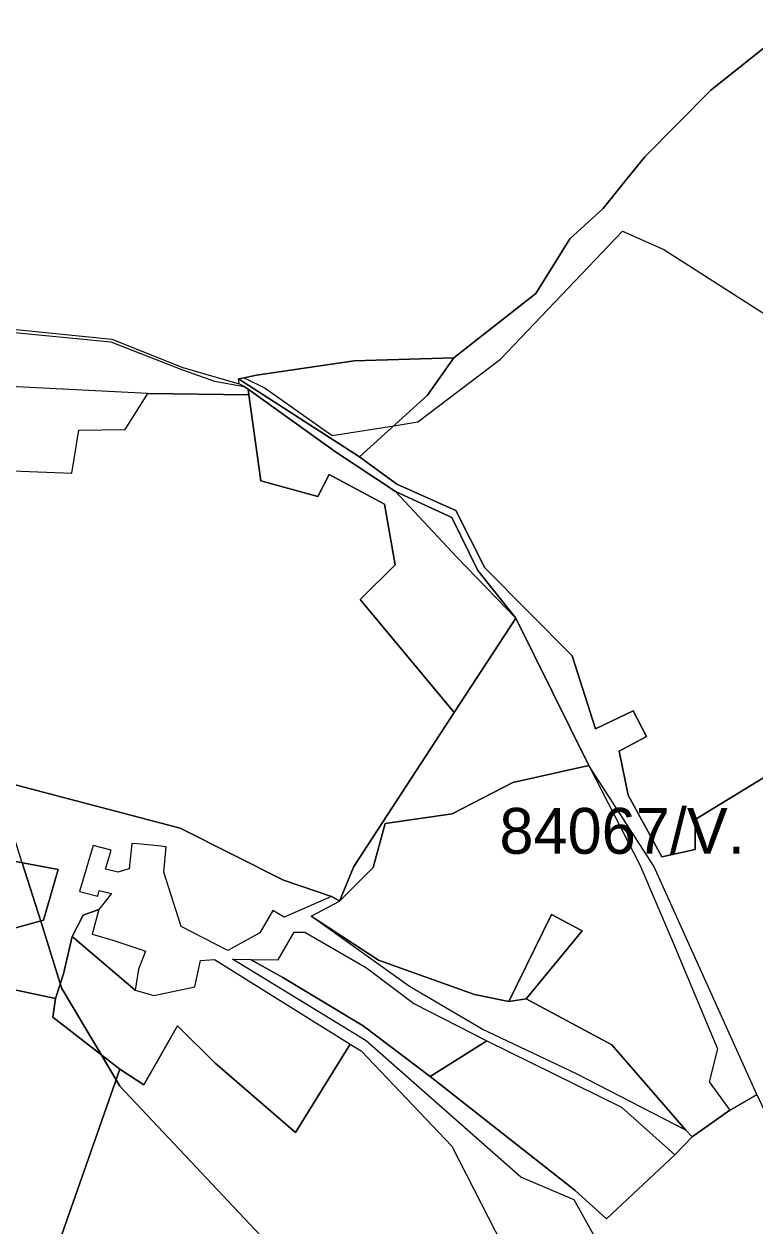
# Model space of a CAD drawing. Extents: x -477304 to -465429, y -1159113 to -1149210.
# Drawn here: x -476359.9 to -476120.7, y -1150940.8 to -1150547.2 of the extents above; entities that cross this region are included whole.
import ezdxf

# ---------------------------------------------------------------- set-up
doc = ezdxf.new("R2010")
doc.units = 0
for name, color, linetype in [('BPEJ_s', 7, 'Continuous'), ('PUPFL_s', 7, 'Continuous'), ('trav_porost_s', 7, 'Continuous')]:
    doc.layers.add(name, color=color, linetype=linetype)

msp = doc.modelspace()

# ---------------------------------------------------------------- linework, layer by layer
at = {"layer": 'BPEJ_s'}
for points in [[(-476107.95, -1150547.2), (-476135.12, -1150568.82), (-476156.76, -1150590.66), (-476163.4, -1150598.92), (-476170.36, -1150607.63), (-476181.22, -1150617.52), (-476192.35, -1150635.43), (-476210.07, -1150649.35), (-476219.17, -1150656.5), (-476251.83, -1150657.52), (-476283.76, -1150662.23), (-476285.3, -1150662.53), (-476287.79, -1150663.02), (-476289.73, -1150663.4), (-476287.82, -1150663.03), (-476287.57, -1150663.16), (-476281, -1150666.5), (-476259, -1150682), (-476238.87, -1150678.77), (-476231, -1150677.5), (-476204, -1150657), (-476164, -1150615), (-476150.5, -1150621), (-476107.5, -1150648.5)], [(-476373.37, -1150646.18), (-476331.18, -1150650.38), (-476307.91, -1150659.69), (-476289.46, -1150665.08), (-476289.73, -1150663.4), (-476287.82, -1150663.03), (-476287.57, -1150663.16), (-476281, -1150666.5), (-476259, -1150682), (-476238.87, -1150678.77), (-476231, -1150677.5), (-476204, -1150657), (-476164, -1150615), (-476150.5, -1150621), (-476107.5, -1150648.5)], [(-476261.1, -1150966.61), (-476328.5, -1150895), (-476329.74, -1150892.92), (-476334.63, -1150884.68), (-476347.5, -1150863), (-476348.01, -1150861.37), (-476354.43, -1150840.98), (-476360.45, -1150821.88), (-476364.5, -1150809), (-476371.2, -1150793.93), (-476374.5, -1150786.5), (-476395, -1150762)], [(-476360.45, -1150821.88), (-476354.43, -1150840.98), (-476348.01, -1150861.37), (-476347.5, -1150863), (-476334.63, -1150884.68), (-476329.74, -1150892.92), (-476328.5, -1150895), (-476261.1, -1150966.61)]]:
    msp.add_lwpolyline(points, dxfattribs=at)
at = {"layer": 'PUPFL_s'}
for points in [[(-476109.7, -1150789.06), (-476140.24, -1150807.74), (-476140.24, -1150817.52), (-476151.2, -1150819.98), (-476162.13, -1150799.7), (-476165.16, -1150785.3), (-476156.19, -1150780.52), (-476160.57, -1150772.14), (-476172.83, -1150777.96), (-476180.54, -1150754.15), (-476209.12, -1150725.33), (-476218.52, -1150706.51), (-476237.9, -1150697.94), (-476250.15, -1150688.99), (-476227.84, -1150668.76), (-476219.17, -1150656.5), (-476210.07, -1150649.35), (-476192.35, -1150635.43), (-476181.22, -1150617.52), (-476170.36, -1150607.63), (-476163.4, -1150598.92), (-476156.76, -1150590.66), (-476135.12, -1150568.82), (-476107.95, -1150547.2)], [(-476120.01, -1150897.77), (-476122.03, -1150893.44), (-476153.81, -1150822.97), (-476175.03, -1150790), (-476198.9, -1150741.72), (-476211.35, -1150726.19), (-476219.89, -1150708.83), (-476238.35, -1150700.34), (-476257.91, -1150687.26), (-476286.58, -1150666.82), (-476287.88, -1150665.9), (-476289.46, -1150665.08), (-476289.73, -1150663.4), (-476250.15, -1150688.99), (-476237.9, -1150697.94), (-476218.52, -1150706.51), (-476209.12, -1150725.33), (-476180.54, -1150754.15), (-476172.83, -1150777.96), (-476160.57, -1150772.14), (-476156.19, -1150780.52), (-476165.16, -1150785.3), (-476162.13, -1150799.7), (-476151.2, -1150819.98), (-476140.24, -1150817.52), (-476140.24, -1150807.74), (-476109.7, -1150789.06)]]:
    msp.add_lwpolyline(points, dxfattribs=at)
for points in [[(-476283.76, -1150662.23), (-476251.83, -1150657.52), (-476219.17, -1150656.5), (-476227.84, -1150668.76), (-476250.15, -1150688.99), (-476289.73, -1150663.4), (-476287.79, -1150663.02), (-476285.3, -1150662.53)], [(-476238.35, -1150700.34), (-476218.34, -1150721.71), (-476198.9, -1150741.72), (-476219.12, -1150772.7), (-476249.87, -1150735.64), (-476238.44, -1150724.3), (-476241.86, -1150704.39), (-476259.97, -1150694.68), (-476263.72, -1150701.89), (-476282.43, -1150696.77), (-476286.32, -1150668.68), (-476286.58, -1150666.82), (-476257.91, -1150687.26)], [(-476218.34, -1150721.71), (-476238.35, -1150700.34), (-476219.89, -1150708.83), (-476211.35, -1150726.19), (-476198.9, -1150741.72)], [(-476199.86, -1150795.58), (-476219.76, -1150805.85), (-476241.71, -1150809.04), (-476245.66, -1150823.44), (-476256.62, -1150834.5), (-476251.98, -1150823.07), (-476219.12, -1150772.7), (-476198.9, -1150741.72), (-476175.03, -1150790)]]:
    msp.add_lwpolyline(points, close=True, dxfattribs=at)
at = {"layer": 'trav_porost_s'}
for points in [[(-476378.07, -1150646.84), (-476365.14, -1150647.97), (-476331.49, -1150651.25), (-476308.07, -1150660.46), (-476297.58, -1150664.15), (-476287.88, -1150665.9), (-476286.58, -1150666.82), (-476286.32, -1150668.68), (-476319.32, -1150668.25), (-476368.8, -1150665.69), (-476386.61, -1150667.75), (-476421.17, -1150662.33), (-476465.43, -1150647.97), (-476496.07, -1150646.31), (-476490.9, -1150642.48), (-476468.87, -1150629.42), (-476490.17, -1150603.42), (-476500.39, -1150593.29), (-476489.18, -1150602.81), (-476474.07, -1150615.61), (-476468.67, -1150621.23), (-476445.25, -1150633.29), (-476428.52, -1150639.56), (-476412.6, -1150645.75)], [(-476219.76, -1150805.85), (-476199.86, -1150795.58), (-476175.03, -1150790), (-476158.38, -1150822.59), (-476147.46, -1150848.09), (-476132.96, -1150882.78), (-476135.65, -1150893.65), (-476128.94, -1150902.85), (-476141.2, -1150911.63), (-476143.34, -1150909.48), (-476167.49, -1150881.47), (-476195.53, -1150866.49), (-476177.27, -1150844.2), (-476187.22, -1150838.84), (-476201.26, -1150867.36), (-476212.41, -1150865.01), (-476243.93, -1150853.79), (-476265.87, -1150839.38), (-476256.62, -1150834.5), (-476245.66, -1150823.44), (-476241.71, -1150809.04)], [(-476353.49, -1150840.72), (-476366.17, -1150844.19), (-476362.73, -1150826.42), (-476381.3, -1150823.35), (-476380.67, -1150818.04), (-476348.74, -1150824.1)], [(-476322.42, -1150856.72), (-476323.55, -1150863.55), (-476344.14, -1150846.01), (-476340.54, -1150839.05), (-476335.4, -1150837.19), (-476337.61, -1150845.31), (-476330.78, -1150847.27), (-476321.94, -1150850.13), (-476320.08, -1150850.87)], [(-476233.78, -1150862.37), (-476265.87, -1150839.38), (-476243.93, -1150853.79), (-476212.41, -1150865.01), (-476201.26, -1150867.36), (-476195.53, -1150866.49), (-476167.49, -1150881.47), (-476143.34, -1150909.48), (-476179.11, -1150890.99), (-476210, -1150876.37)], [(-476201.26, -1150867.36), (-476187.22, -1150838.84), (-476177.27, -1150844.2), (-476195.53, -1150866.49)], [(-476349.63, -1150866.32), (-476347.01, -1150858.29), (-476344.14, -1150846.01), (-476323.55, -1150863.55), (-476317.43, -1150865.35), (-476304.02, -1150862.54), (-476302.1, -1150853.85), (-476297.58, -1150853.59), (-476253.14, -1150881.28), (-476271, -1150910.18), (-476297.42, -1150887.37), (-476309.67, -1150875.31), (-476320.67, -1150894.56), (-476328.51, -1150889.43), (-476350.43, -1150872.41)], [(-476247.78, -1150856.3), (-476232.27, -1150867.96), (-476208.42, -1150880.16), (-476226.98, -1150891.89), (-476248.92, -1150875.23), (-476275.15, -1150859.5), (-476285.76, -1150853.51), (-476276.66, -1150853.63), (-476271.43, -1150844.64), (-476268, -1150844.58)], [(-476291.66, -1150853.44), (-476285.76, -1150853.51), (-476275.15, -1150859.5), (-476248.92, -1150875.23), (-476226.98, -1150891.89), (-476179.52, -1150929.19), (-476169.27, -1150938.5), (-476146.89, -1150917.53), (-476141.2, -1150911.63), (-476128.94, -1150902.85), (-476120.01, -1150897.77), (-476105.17, -1150929.65), (-476058.51, -1150979.19), (-476050.49, -1150992.18), (-476075.81, -1150994.87), (-476131.48, -1150994.9), (-476151.58, -1150982.94), (-476179.85, -1150932.3), (-476197.3, -1150924.8), (-476247.95, -1150880.21)], [(-476371.22, -1150958.62), (-476371.72, -1150951.61), (-476371.19, -1150945.92), (-476384.56, -1150909.96), (-476384.75, -1150879.91), (-476385.1, -1150858.82), (-476349.63, -1150866.32), (-476350.43, -1150872.41), (-476328.51, -1150889.43), (-476357.03, -1150970.64)], [(-476226.98, -1150891.89), (-476208.42, -1150880.16), (-476164.31, -1150901.91), (-476146.89, -1150917.53), (-476169.27, -1150938.5), (-476179.52, -1150929.19)]]:
    msp.add_lwpolyline(points, close=True, dxfattribs=at)
for points in [[(-476380.43, -1150692.92), (-476344.28, -1150694.31), (-476341.95, -1150680.22), (-476326.8, -1150680.02), (-476319.32, -1150668.25), (-476286.32, -1150668.68), (-476282.43, -1150696.77), (-476263.72, -1150701.89), (-476259.97, -1150694.68), (-476241.86, -1150704.39), (-476238.44, -1150724.3), (-476249.87, -1150735.64), (-476219.12, -1150772.7), (-476251.98, -1150823.07), (-476256.62, -1150834.5), (-476259.27, -1150832.88), (-476274.99, -1150827.56), (-476308.75, -1150810.6), (-476368.73, -1150794.88)], [(-476368.73, -1150794.88), (-476308.75, -1150810.6), (-476274.99, -1150827.56), (-476259.27, -1150832.88), (-476274.71, -1150839.67), (-476278.46, -1150837.51), (-476282.68, -1150844.84), (-476293.17, -1150850.64), (-476308.51, -1150842.71), (-476314.18, -1150824.92), (-476313.37, -1150816.64), (-476315.01, -1150816.48), (-476322.76, -1150815.72), (-476324.65, -1150815.54), (-476325.46, -1150823.87), (-476329.18, -1150824.92), (-476333.18, -1150823.94), (-476331.36, -1150817.75), (-476337.3, -1150816.2), (-476341.72, -1150831.28), (-476335.78, -1150832.83), (-476335.25, -1150831.01), (-476331.25, -1150831.99), (-476335.4, -1150837.19), (-476340.54, -1150839.05), (-476344.14, -1150846.01), (-476347.01, -1150858.29), (-476349.63, -1150866.32), (-476385.1, -1150858.82)], [(-476366.17, -1150844.19), (-476353.49, -1150840.72), (-476348.74, -1150824.1), (-476380.67, -1150818.04)], [(-476357.03, -1150970.64), (-476328.51, -1150889.43), (-476320.67, -1150894.56), (-476309.67, -1150875.31), (-476297.42, -1150887.37), (-476271, -1150910.18), (-476253.14, -1150881.28), (-476249.59, -1150883.51), (-476219.86, -1150914.67), (-476198.41, -1150956.73)]]:
    msp.add_lwpolyline(points, dxfattribs=at)

# ---------------------------------------------------------------- texts
at = {"layer": 'BPEJ_s'}
msp.add_text('84067/V.', height=15, dxfattribs=at).set_placement((-476204.3, -1150818.93))

doc.saveas('drawing.dxf')
